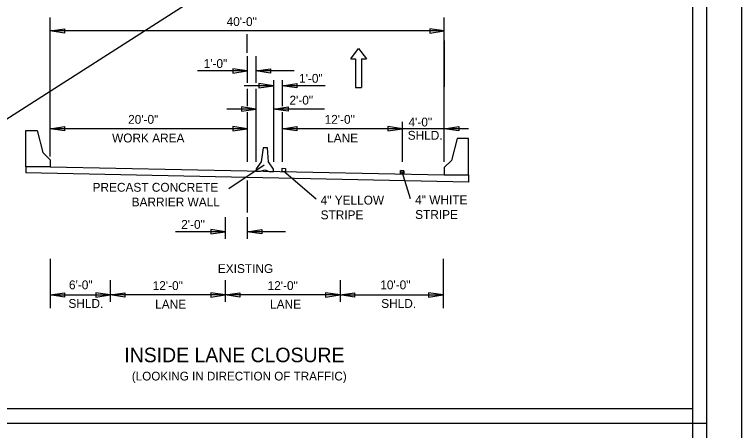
# Model space of a CAD drawing. Extents: x 13528 to 25043, y 7635 to 10612.
# Drawn here: x 22933 to 23433, y 10073 to 10360 of the extents above; entities that cross this region are included whole.
import ezdxf

# ---------------------------------------------------------------- set-up
doc = ezdxf.new("R2010")
doc.units = 0
for name, color, linetype in [('Default', 7, 'Continuous'), ('R_Border Plan-Plan', 7, 'Continuous'), ('R_Draft', 7, 'Continuous'), ('R_Revision Date Text', 7, 'Continuous'), ('STAMP_PE_TAEGTMEYER-SIGNATURE', 7, 'Continuous'), ('STAMP_PRELIMINARY', 7, 'Continuous')]:
    doc.layers.add(name, color=color, linetype=linetype)

msp = doc.modelspace()

# ---------------------------------------------------------------- linework, layer by layer
at = {"layer": 'Default'}
for p, q in [((23433.27, 10611.55), (21766.57, 9544.86)), ((22957.01, 10261.97), (22957.01, 10357.8)), ((23228.56, 10258.31), (23228.56, 10357.8)), ((23228.56, 10348.48), (22957.01, 10348.48)), ((23092.84, 10333.29), (23092.84, 10346.15)), ((23228.56, 10341.99), (23228.56, 10309.89)), ((23092.84, 10331.11), (23092.84, 10312.67)), ((23098.87, 10331.11), (23098.87, 10312.67)), ((23092.84, 10320.94), (23058.68, 10320.94)), ((23125.23, 10320.94), (23098.87, 10320.94)), ((23110.93, 10310.75), (23090.76, 10310.75)), ((23110.93, 10314.49), (23110.93, 10307.01)), ((23116.96, 10314.49), (23116.96, 10296.65)), ((23146.54, 10310.75), (23116.96, 10310.75)), ((23092.84, 10308.67), (23092.84, 10296.57)), ((23098.87, 10308.67), (23098.87, 10258.31)), ((23110.93, 10307.01), (23110.93, 10258.31)), ((23098.87, 10294.65), (23078.7, 10294.65)), ((23092.84, 10292.57), (23092.84, 10282.88)), ((23145.96, 10294.65), (23110.93, 10294.65)), ((23116.96, 10292.65), (23116.96, 10258.31)), ((23199.7, 10258.31), (23199.7, 10285.88)), ((23092.84, 10281.17), (22957.01, 10281.17)), ((23092.84, 10282.88), (23092.84, 10263.18)), ((23245.35, 10281.17), (23116.96, 10281.17)), ((23092.84, 10276.02), (23092.84, 10258.31)), ((23080.09, 10239.99), (23104.49, 10256.31)), ((23116.96, 10251.62), (23117.01, 10253.91)), ((23116.96, 10251.62), (23117.01, 10253.91)), ((23119.25, 10251.57), (23116.96, 10251.62)), ((23117.01, 10253.91), (23119.3, 10253.87)), ((23117.01, 10253.91), (23119.3, 10253.87)), ((23140.24, 10232.54), (23118.11, 10251.62)), ((23119.3, 10253.87), (23119.25, 10251.57)), ((23119.3, 10253.87), (23119.25, 10251.57)), ((23198.42, 10252.29), (23198.37, 10249.99)), ((23198.37, 10249.99), (23198.42, 10252.29)), ((23200.66, 10249.95), (23198.37, 10249.99)), ((23200.71, 10252.24), (23198.42, 10252.29)), ((23198.42, 10252.29), (23200.71, 10252.24)), ((23205.36, 10232.77), (23199.52, 10251.42)), ((23200.66, 10249.95), (23200.71, 10252.24)), ((23200.71, 10252.24), (23200.66, 10249.95)), ((23092.84, 10245.54), (23092.84, 10223.36)), ((23077.67, 10220.35), (23077.67, 10205.39)), ((23092.84, 10220.35), (23092.84, 10205.39)), ((23077.67, 10210.18), (23043.51, 10210.18)), ((23119.2, 10210.18), (23092.84, 10210.18)), ((22957.01, 10191.48), (22957.01, 10157.61)), ((23227.76, 10191.48), (23227.76, 10157.61)), ((22957.01, 10176.89), (22957.01, 10161.93)), ((22998.51, 10176.89), (22998.51, 10161.93)), ((23077.67, 10176.89), (23077.67, 10161.93)), ((23156.83, 10176.89), (23156.83, 10161.93)), ((22957.01, 10166.73), (22998.51, 10166.73)), ((23077.67, 10166.73), (22998.51, 10166.73)), ((23156.83, 10166.73), (23077.67, 10166.73)), ((23156.83, 10166.73), (23227.76, 10166.73))]:
    msp.add_line(p, q, dxfattribs=at)
for points in [[(22957.01, 10348.48), (22967.01, 10349.98), (22967.01, 10346.98)], [(23228.56, 10348.48), (23218.56, 10349.98), (23218.56, 10346.98)], [(23092.84, 10320.94), (23082.84, 10322.44), (23082.84, 10319.44)], [(23098.87, 10320.94), (23108.87, 10322.44), (23108.87, 10319.44)], [(23110.93, 10310.75), (23100.93, 10312.25), (23100.93, 10309.25)], [(23116.96, 10310.75), (23126.96, 10312.25), (23126.96, 10309.25)], [(23098.87, 10294.65), (23088.87, 10296.15), (23088.87, 10293.15)], [(23110.93, 10294.65), (23120.93, 10296.15), (23120.93, 10293.15)], [(22957.01, 10281.17), (22967.01, 10282.67), (22967.01, 10279.67)], [(23092.84, 10281.17), (23082.84, 10282.67), (23082.84, 10279.67)], [(23116.96, 10281.17), (23126.96, 10282.67), (23126.96, 10279.67)], [(23199.7, 10281.17), (23189.7, 10282.67), (23189.7, 10279.67)], [(23228.56, 10281.17), (23238.56, 10282.67), (23238.56, 10279.67)], [(23077.67, 10210.18), (23067.67, 10211.68), (23067.67, 10208.68)], [(23092.84, 10210.18), (23102.84, 10211.68), (23102.84, 10208.68)], [(22957.01, 10166.73), (22967.01, 10168.23), (22967.01, 10165.23)], [(22998.51, 10166.73), (22988.51, 10168.23), (22988.51, 10165.23)], [(22998.51, 10166.73), (23008.51, 10168.23), (23008.51, 10165.23)], [(23077.67, 10166.73), (23067.67, 10168.23), (23067.67, 10165.23)], [(23077.67, 10166.73), (23087.67, 10168.23), (23087.67, 10165.23)], [(23156.83, 10166.73), (23146.83, 10168.23), (23146.83, 10165.23)], [(23156.83, 10166.73), (23166.83, 10168.23), (23166.83, 10165.23)], [(23227.76, 10166.73), (23217.76, 10168.23), (23217.76, 10165.23)]]:
    msp.add_lwpolyline(points, close=True, dxfattribs=at)
at = {"layer": 'R_Border Plan-Plan'}
msp.add_line((21828.61, 10078.42), (23409.51, 10078.42), dxfattribs=at)
at = {"layer": 'R_Draft'}
msp.add_line((23409.51, 9564.77), (23409.51, 10592.07), dxfattribs=at)
at = {"layer": 'R_Revision Date Text'}
for points in [[(21766.57, 10611.55), (23433.27, 10611.55), (23433.27, 9544.86), (21766.57, 9544.86)], [(23399.51, 10088.42), (21838.61, 10088.42), (21838.61, 10582.07), (23086.31, 10582.07), (23086.31, 10532.67), (23174.01, 10532.67), (23294.51, 10532.67), (23294.51, 10421.01), (23399.51, 10421.01)], [(21838.61, 10582.07), (23086.31, 10582.07), (23086.31, 10532.67), (23174.01, 10532.67), (23294.51, 10532.67), (23294.51, 10421.01), (23399.51, 10421.01), (23399.51, 9574.77), (21838.61, 9574.77)]]:
    msp.add_lwpolyline(points, close=True, dxfattribs=at)
at = {"layer": 'STAMP_PE_TAEGTMEYER-SIGNATURE'}
for p, q in [((23164.09, 10329.36), (23169.51, 10336.4)), ((23169.51, 10336.4), (23174.93, 10329.36)), ((23164.09, 10329.36), (23167.48, 10329.36)), ((23167.48, 10329.36), (23167.48, 10309.41)), ((23171.54, 10329.36), (23171.54, 10309.41)), ((23171.54, 10329.36), (23174.93, 10329.36)), ((23167.48, 10309.41), (23171.54, 10309.41))]:
    msp.add_line(p, q, dxfattribs=at)
at = {"layer": 'STAMP_PRELIMINARY'}
for p, q in [((23103.73, 10267.97), (23102.53, 10258.44)), ((23106.74, 10267.91), (23103.73, 10267.97)), ((23107.56, 10258.34), (23106.74, 10267.91)), ((23102.53, 10258.44), (23098.92, 10253.49)), ((23110.98, 10253.25), (23107.56, 10258.34)), ((22940.33, 10254.82), (22940.33, 10250.74)), ((22957.11, 10254.82), (22940.33, 10254.82)), ((23245.25, 10244.29), (22940.33, 10250.74)), ((22957.11, 10254.82), (23228.56, 10249.39)), ((23098.92, 10253.49), (23098.87, 10251.98)), ((23098.87, 10251.98), (23101.88, 10251.92)), ((23101.88, 10251.92), (23104.92, 10252.87)), ((23104.92, 10252.87), (23107.91, 10251.8)), ((23107.91, 10251.8), (23110.93, 10251.74)), ((23110.93, 10251.74), (23110.98, 10253.25)), ((23228.56, 10249.39), (23245.35, 10249.39)), ((23245.35, 10249.38), (23245.35, 10244.29))]:
    msp.add_line(p, q, dxfattribs=at)
for points in [[(22940.33, 10254.81), (22940.33, 10279.81), (22948.15, 10279.81), (22952.12, 10264.81)], [(23245.35, 10249.38), (23245.35, 10274.38), (23237.52, 10274.38), (23233.55, 10259.38)], [(22952.12, 10264.81), (22957.12, 10259.81), (22957.11, 10254.82)], [(23233.55, 10259.38), (23228.55, 10254.38), (23228.56, 10249.39)]]:
    msp.add_lwpolyline(points, dxfattribs=at)

# ---------------------------------------------------------------- texts
at = {"layer": 'Default'}
for s, height, p in [('40\'-0"', 6.1, (23078.64, 10351.84)), ('1\'-0"', 6.1, (23062.8, 10322.97)), ('1\'-0"', 6.1, (23128.56, 10312.78)), ('2\'-0"', 6.1, (23121.95, 10297.76)), ('20\'-0"', 6.1, (23010.78, 10284.53)), ('12\'-0"', 6.1, (23146.15, 10284.53)), ('4\'-0" ', 6.1, (23203.94, 10282.7)), ('WORK AREA', 6.1, (22999.72, 10271.71)), ('LANE', 6.1, (23147.86, 10271.71)), ('SHLD.', 6.1, (23203.38, 10273.55)), ('PRECAST CONCRETE', 6.1, (22986.32, 10237.76)), ('4" YELLOW', 6.1, (23143.4, 10228.91)), ('4" WHITE', 6.1, (23208.52, 10229.15)), ('BARRIER WALL', 6.1, (23013.23, 10227.63)), ('STRIPE', 6.1, (23143.4, 10218.79)), ('STRIPE', 6.1, (23208.52, 10219.02)), ('2\'-0"', 6.1, (23047.36, 10212.21)), ('EXISTING', 6.1, (23072.6, 10181.8)), ('6\'-0"', 6.1, (22970.04, 10170.6)), ('12\'-0"', 6.1, (23027.7, 10170.09)), ('12\'-0"', 6.1, (23106.86, 10170.09)), ('10\'-0"', 6.1, (23184.49, 10170.6)), ('SHLD.', 6.1, (22969.67, 10157.8)), ('LANE', 6.1, (23029.41, 10157.26)), ('LANE', 6.1, (23108.57, 10157.26)), ('SHLD.', 6.1, (23185.13, 10157.8)), ('INSIDE LANE CLOSURE ', 10.002, (23008.18, 10120.4)), ('(LOOKING IN DIRECTION OF TRAFFIC)', 6, (23013.36, 10107.83))]:
    msp.add_text(s, height=height, dxfattribs=at).set_placement(p)

doc.saveas('drawing.dxf')
